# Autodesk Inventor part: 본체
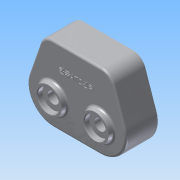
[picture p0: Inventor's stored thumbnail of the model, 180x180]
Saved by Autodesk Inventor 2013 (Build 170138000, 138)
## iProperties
Created: 2014-12
Part Number: 본체
Material: 알루미늄 6061
Document SubType Name: Modeling
Designer: kb543-18
Density: 2.71 g/cm^3
Mass: 613.107 g
Surface Area: 664.972 cm^2
Volume: 226.239 cm^3
Author: kb543-18
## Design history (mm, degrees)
sketch "스케치1"
  geometry: L1 (-34.162, 36)-(34.162, 36); L2 (51.181, 23.862)-(66.565, -20.803); L3 (-51.181, 23.862)-(-66.565, -20.803); L4 (-32.527, -68.527)-(32.527, -68.527); L5 (0, 0)-(-32.527, -32.527); L6 (0, 0)-(32.527, -32.527); L7 (0, 0)-(0, -20.962); A1 r 46 centre (0, 0) between (-32.527, -32.527) and (32.527, -32.527); A2 r 36 centre (-32.527, -32.527) between (-66.565, -20.803) and (-32.527, -68.527); A3 r 36 centre (32.527, -32.527) between (32.527, -68.527) and (66.565, -20.803); A4 r 18 centre (-34.162, 18) between (-34.162, 36) and (-51.181, 23.862); A5 r 18 centre (34.162, 18) between (51.181, 23.862) and (34.162, 36); 3 further points
  constraints: 14 end point, 10 point on circle, 7 tangent, 5 centre point, 4 point on line, 3 coincident, 2 horizontal, 1 equal radius, 1 perpendicular
  dimensions: "d0" = 36 distance from line of L1 point (0, 0); "d1" = 92 diameter of A1; "d2" = 45 deg angle of L7 L5; "d3" = 90 deg angle of L6 L5; "d4" = 72 diameter of A2; "d5" = 72 diameter of A3; "d6" = 94 distance of point (47, 36) point (-47, 36); "d7" = 47 horizontal distance of point (-47, 36) point (0, 0); "d8" = 18 radius of A4
extrude "돌출1" new body sketch "스케치1" distance "d9" = 44; taper "d10" = 0 deg
feature "쉘1" dims "d11" = 5
sketch "스케치4"
  geometry: 1 further point
sketch "스케치5"
  geometry: L1 (32.527, -63.527)-(-32.527, -63.527) reference; L2 (-61.837, -22.432)-(-46.453, 22.233) reference; L3 (-34.162, 31)-(34.162, 31) reference; L4 (66.565, -20.803)-(51.181, 23.862) reference; L5 (34.162, 36)-(-34.162, 36) reference; L6 (0, 31)-(0, 0); L7 (-8, -63.527)-(8, -63.527); L8 (49.095, 14.564)-(54.305, -0.564); L9 (-49.095, 14.564)-(-54.305, -0.564); A1 r 8 centre (-51.7, 7) between (-54.305, -0.564) and (-49.095, 14.564); A2 r 8 centre (51.7, 7) between (49.095, 14.564) and (54.305, -0.564); A3 r 8 centre (0, -63.527) between (8, -63.527) and (-8, -63.527)
  constraints: 8 end point, 6 point on circle, 5 point on line, 3 centre point, 3 symmetric about line, 2 collinear, 2 midpoint, 1 parallel, 1 perpendicular, 1 other
  dimensions: "d12" = 16 diameter of A1; "d13" = 29 distance from line of A1.centre L5
extrude "돌출2" join sketch "스케치5" stored distance "d15" = 44; taper "d16" = 0 deg
sketch "스케치6"
  geometry: L1 (66.689, -94.527)-(42.162, -94.527) reference; L2 (88.467, -31.564)-(95.999, -53.432) reference; L3 (80.615, -8.767)-(83.257, -16.436) reference; L4 (0, 0)-(68.324, 0) reference; L5 (-14.933, -16.436)-(-12.291, -8.767) reference; L6 (-27.675, -53.432)-(-20.143, -31.564) reference; L7 (26.162, -94.527)-(1.635, -94.527) reference; A1 r 8 centre (34.162, -94.527) between (42.162, -94.527) and (26.162, -94.527) reference; A2 r 31 centre (66.689, -63.527) between (66.689, -94.527) and (95.999, -53.432) reference; A3 r 8 centre (85.862, -24) between (83.257, -16.436) and (88.467, -31.564) reference; A4 r 13 centre (68.324, -13) between (80.615, -8.767) and (68.324, 0) reference; A5 r 13 centre (0, -13) between (0, 0) and (-12.291, -8.767) reference; A6 r 8 centre (-17.538, -24) between (-20.143, -31.564) and (-14.933, -16.436) reference; A7 r 31 centre (1.635, -63.527) between (-27.675, -53.432) and (1.635, -94.527) reference; 1 further point
extrude "돌출3" join sketch "스케치6" distance "d17" = 5; taper "d18" = 0 deg
sketch "스케치10"
  geometry: C1 r 24 at (34.162, -31); C2 r 24 at (1.635, -63.527); C3 r 24 at (66.689, -63.527); A1 r 31 centre (66.689, -63.527) between (66.689, -94.527) and (95.999, -53.432) reference; A2 r 31 centre (1.635, -63.527) between (-27.675, -53.432) and (1.635, -94.527) reference; 1 further point
  constraints: 3 centre point, 3 coincident
  dimensions: "d20" = 48 diameter of C1; "d22" = 48 diameter of C2; "d23" = 48 diameter of C3
extrude "돌출4" join sketch "스케치10" distance "d24" = 11; taper "d25" = 0 deg
sketch "스케치12"
  geometry: C1 r 20 at (32.527, 32.527); C2 r 20 at (-32.527, 32.527); A1 r 36 centre (-32.527, 32.527) between (-32.527, 68.527) and (-66.565, 20.803) reference; A2 r 36 centre (32.527, 32.527) between (66.565, 20.803) and (32.527, 68.527) reference; 1 further point
  constraints: 2 centre point, 2 coincident
  dimensions: "d26" = 40 diameter of C1; "d27" = 40 diameter of C2
extrude "돌출5" join sketch "스케치12" distance "d28" = 7; taper "d29" = -10 deg
sketch "스케치13"
  geometry: L1 (-11.908, 0)-(65.053, 0); L2 (0, 36)-(44, 36) reference; L3 (23, 20)-(34.7, 20); L4 (35, 19.7)-(35, 10); L5 (35, 10)-(35, 10); L6 (38, 7)-(38, 0); L7 (23, 24)-(23, -11.416) reference; L8 (23, 20)-(23, 0); A1 r 0.3 centre (34.7, 19.7) between (35, 19.7) and (34.7, 20); A2 r 3 centre (35, 7) between (38, 7) and (35, 10); 1 further point
  constraints: 12 end point, 4 point on circle, 4 point on line, 4 tangent, 2 centre point, 2 parallel, 2 perpendicular, 1 horizontal
  dimensions: "d30" = 36 distance between parallel lines of L1 L2; "d31" = 12 distance between parallel lines of L4 L7; "d32" = 3 distance between parallel lines of L6 L4; "d33" = 40 diameter of L3 L1; "d34" = 20 diameter of L5 L1; "d35" = 0.3 radius of A1; "d36" = 3 radius of A2
revolve "회전1" sketch "스케치13" stored, may be unused: angle "d37" = 90 deg
sketch "스케치14"
  geometry: C1 r 20 at (34.162, -31) reference; A1 r 24 centre (34.162, -31) between (22.746, -52.111) and (45.578, -52.111) reference; A2 r 24 centre (66.689, -63.527) between (45.578, -52.111) and (55.273, -42.416) reference; A3 r 24 centre (34.162, -31) between (55.273, -42.416) and (13.051, -42.416) reference; A4 r 24 centre (1.635, -63.527) between (13.051, -42.416) and (22.746, -52.111) reference
node "작업 평면2"
sketch "스케치16"
  geometry: L1 (0, 0)-(28, 0); L2 (21, 20)-(28, 18.766) reference; L3 (11, 21.111)-(0, 21.111) reference; L4 (0, 11.416)-(0, 21.111) reference; L5 (0, 11.416)-(11, 11.416) reference; L6 (11, 21.111)-(11, 11.416) reference; L7 (21, -20)-(28, -18.766) reference; L8 (28, 15)-(21.1, 15); L9 (21, 14.9)-(21, 7.75); L10 (21, 7.75)-(11, 7.75); L11 (0, 17.5)-(10.7, 17.5); L12 (11, 7.75)-(11, 17.2); L13 (28, -18.766)-(28, 18.766) reference; L14 (0, 17.5)-(0, 0); L15 (28, 15)-(28, 0); A1 r 0.1 centre (21.1, 14.9) between (21.1, 15) and (21, 14.9); A2 r 0.3 centre (10.7, 17.2) between (11, 17.2) and (10.7, 17.5); 3 further points
  constraints: 16 end point, 5 point on line, 4 parallel, 4 point on circle, 4 tangent, 2 centre point, 2 perpendicular, 1 collinear, 1 horizontal, 1 midpoint
  dimensions: "d44" = 7 distance between parallel lines of L9 L13; "d46" = 30 diameter of L8 L1; "d47" = 15.5 diameter of L10 L1; "d48" = 35 diameter of L11 L1; "d49" = 10 distance between parallel lines of L12 L9; "d51" = 0.1 radius of A1; "d52" = 0.3 radius of A2
revolve "회전2" sketch "스케치16" stored, may be unused: angle "d50" = 90 deg
chamfer "모따기1" distance "d53" = 1; stored, may be unused: second distance "d54" = 2, angle "d55" = 45 deg
sketch "스케치18"
  geometry: A1 r 8 centre (51.7, 7) between (49.095, 14.564) and (54.305, -0.564) reference; A2 r 8 centre (0, -63.527) between (8, -63.527) and (-8, -63.527) reference; A3 r 8 centre (-51.7, 7) between (-54.305, -0.564) and (-49.095, 14.564) reference; 4 further points
  constraints: 3 coincident
hole "구멍1" sketch "스케치18" at (-51.7, 7), (51.7, 7), (0, -63.527) diameter "d56" = 4.134; stored, may be unused: countersink angle "d60" = 90 deg, drill point angle "d62" = 118 deg; dims "d57" = 20, "d58" = 4, "d59" = 2, "d61" = 23
fillet "모깎기1" dims "d63" = 3
fillet "모깎기2" dims "d64" = 3
fillet "모깎기3" dims "d65" = 3
fillet "모깎기4" dims "d66" = 3
sketch "스케치19"
  geometry: 1 further point
fillet "모깎기5" dims "d67" = 3
sketch "스케치20"
  geometry: L1 (-34.162, -36)-(34.162, -36) reference; 2 further points
  constraints: 1 other
  dimensions: "d68" = 30 distance from line of L1 point (0, -6); "d69" = 0 horizontal distance of point (0, 0) point (0, -6)
feature "엠보싱1" sketch "스케치20" dims "d70" = 1, "d71" = 0
node "솔리드1"
mirror "대칭1"
node "투영된 루프4"
node "작업 평면3"
other parameters: "d14" = 16
